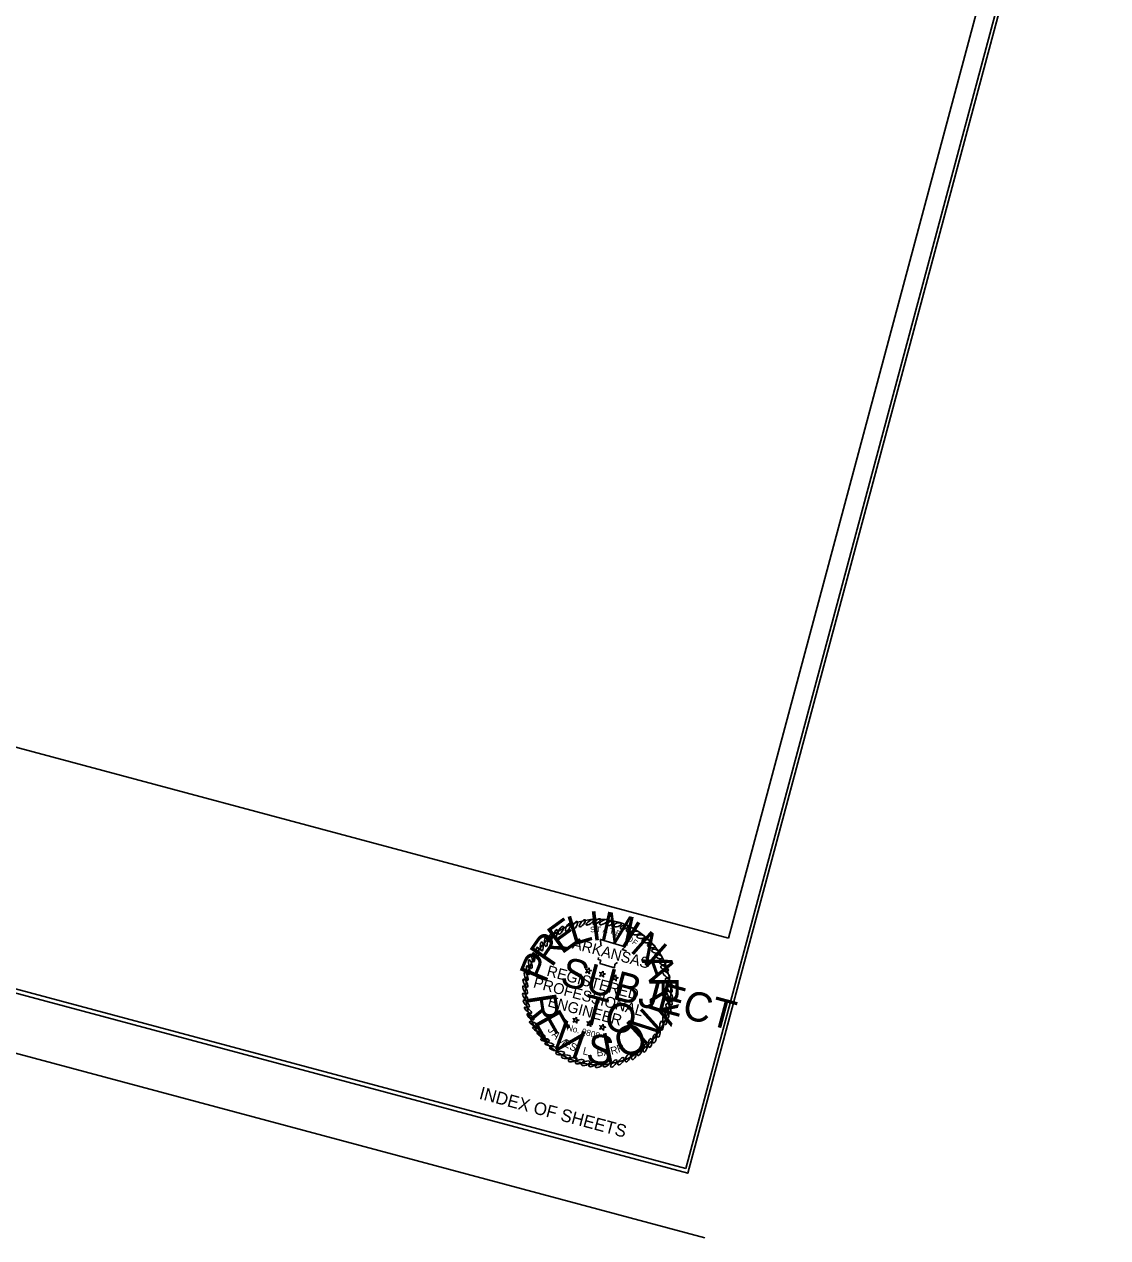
# Model space of a CAD drawing. Extents: x 1272249 to 1274802, y 195141 to 198564.
# Drawn here: x 1273526 to 1274221, y 195141 to 195920 of the extents above; entities that cross this region are included whole.
import ezdxf

# ---------------------------------------------------------------- set-up
doc = ezdxf.new("R2010")
doc.units = 0
for name, color, linetype in [('R_Border', 7, 'Continuous'), ('R_Border Notes', 7, 'Continuous'), ('R_Border PE', 7, 'Continuous'), ('R_Border Prem', 7, 'Continuous'), ('R_No Plot', 7, 'Continuous'), ('T_Drafting', 7, 'Continuous')]:
    doc.layers.add(name, color=color, linetype=linetype)

msp = doc.modelspace()

# ---------------------------------------------------------------- linework, layer by layer
at = {"layer": 'R_Border'}
for p, q in [((1273950.19, 195185.8), (1274218.04, 196185.54)), ((1272249.46, 195600.35), (1273962.36, 195141.49)), ((1273950.19, 195185.8), (1272411.61, 195598.06))]:
    msp.add_line(p, q, dxfattribs=at)
at = {"layer": 'R_Border PE'}
for points in [[(1273895.62, 195329.33), (1273895.45, 195332.76), (1273911.2, 195328.07), (1273909.45, 195326.25), (1273911.85, 195325.45), (1273911.62, 195325.2)], [(1273906.44, 195317.93), (1273904.75, 195316.87), (1273904.46, 195314.6), (1273895.05, 195317.43), (1273895.59, 195319.48), (1273893.89, 195319.93), (1273894.23, 195321.2)]]:
    msp.add_lwpolyline(points, dxfattribs=at)
for points in [[(1273888.14, 195314.64), (1273888.2, 195313.11), (1273889.61, 195312.73), (1273888.25, 195312.32), (1273888.3, 195310.74), (1273887.41, 195311.92), (1273886.01, 195311.35), (1273886.84, 195312.7), (1273885.87, 195313.74), (1273887.33, 195313.35)], [(1273897.09, 195312.4), (1273897.19, 195311.02), (1273898.5, 195310.67), (1273897.24, 195310.06), (1273897.33, 195308.63), (1273896.36, 195309.68), (1273894.99, 195309.26), (1273895.78, 195310.46), (1273894.9, 195311.63), (1273896.31, 195311.25)], [(1273905.27, 195310.05), (1273905.33, 195308.52), (1273906.74, 195308.15), (1273905.43, 195307.72), (1273905.47, 195306.14), (1273904.54, 195307.33), (1273903.14, 195306.76), (1273903.97, 195308.11), (1273903, 195309.15), (1273904.46, 195308.76)], [(1273880.13, 195282.99), (1273880.13, 195281.43), (1273881.59, 195281.04), (1273880.24, 195280.67), (1273880.29, 195279.09), (1273879.4, 195280.27), (1273878, 195279.71), (1273878.83, 195281.05), (1273877.84, 195282.04), (1273879.3, 195281.65)], [(1273889.08, 195280.75), (1273889.16, 195279.32), (1273890.48, 195278.97), (1273889.09, 195278.46), (1273889.32, 195276.99), (1273888.35, 195278.03), (1273886.98, 195277.61), (1273887.77, 195278.81), (1273886.88, 195279.94), (1273888.29, 195279.56)], [(1273897.26, 195278.4), (1273897.31, 195276.83), (1273898.72, 195276.45), (1273897.42, 195276.07), (1273897.42, 195274.5), (1273896.53, 195275.68), (1273895.13, 195275.12), (1273895.96, 195276.46), (1273894.97, 195277.45), (1273896.43, 195277.06)]]:
    msp.add_lwpolyline(points, close=True, dxfattribs=at)
for centre, major_axis, ratio in [((1273883.79, 195343.04), (-1.87, -2.18), 0.329518), ((1273888.68, 195343.79), (-2.32, -1.69), 0.329518), ((1273893.02, 195344.16), (-2.34, -1.66), 0.329518), ((1273897.51, 195343.9), (-2.78, -1.45), 0.348728), ((1273866.66, 195336.26), (-0.75, -2.78), 0.322879), ((1273869.96, 195338.55), (-1.46, -2.47), 0.391724), ((1273874.64, 195340.57), (-1.46, -2.47), 0.394697), ((1273879.09, 195341.75), (-1.46, -2.47), 0.375751), ((1273901.65, 195343.06), (-2.28, -0.97), 0.44237), ((1273906.46, 195342.19), (-2.37, -0.65), 0.475469), ((1273910.58, 195340.63), (-2.37, -0.65), 0.475469), ((1273914.34, 195338.86), (-2.37, -0.65), 0.475469), ((1273917.96, 195336.87), (-2.45, -0.11), 0.475469), ((1273857.77, 195328.25), (0.05, -2.87), 0.322879), ((1273860.47, 195331), (0.05, -2.87), 0.322879), ((1273863.55, 195333.94), (-0.75, -2.78), 0.322879), ((1273921.21, 195334.5), (-2.45, 0.19), 0.475469), ((1273924.56, 195331.75), (-2.42, 0.43), 0.475469), ((1273928.05, 195328.57), (-2.42, 0.43), 0.475469), ((1273852.44, 195321.34), (0.05, -2.87), 0.322879), ((1273855.02, 195324.85), (0.05, -2.87), 0.322879), ((1273930.59, 195325.2), (-2.35, 0.69), 0.475469), ((1273932.64, 195321.88), (-2.38, 1), 0.451028), ((1273849.13, 195313.11), (0.85, -2.75), 0.322879), ((1273850.42, 195316.96), (0.85, -2.75), 0.322879), ((1273934.88, 195317.98), (-2.36, 1.25), 0.436264), ((1273936.57, 195314.21), (-2.37, 1.46), 0.418512), ((1273847.33, 195304.67), (1.37, -2.53), 0.322879), ((1273847.78, 195309.07), (0.85, -2.75), 0.322879), ((1273937.71, 195310.16), (-2.07, 2), 0.40589), ((1273939.12, 195305.65), (-1.84, 2.21), 0.40589), ((1273847.17, 195300.38), (1.37, -2.53), 0.322879), ((1273939.58, 195301.36), (-1.6, 2.38), 0.40589), ((1273939.84, 195297.21), (-1.6, 2.38), 0.40589), ((1273847.25, 195295.75), (1.6, -2.39), 0.322879), ((1273847.9, 195291.65), (1.85, -2.2), 0.322879), ((1273939.01, 195289.09), (-1.12, 2.65), 0.40589), ((1273939.68, 195293.25), (-1.48, 2.46), 0.40589), ((1273848.95, 195287.36), (2.17, -1.88), 0.322879), ((1273850.57, 195283.12), (2.17, -1.88), 0.322879), ((1273936.65, 195280.96), (-0.44, 2.84), 0.40589), ((1273938.01, 195285.04), (-0.7, 2.79), 0.40589), ((1273852.52, 195278.62), (2.56, -1.31), 0.322879), ((1273854.52, 195275.07), (2.56, -1.31), 0.322879), ((1273932.54, 195273.03), (0.24, 2.86), 0.40589), ((1273934.65, 195277.41), (0, 2.87), 0.40589), ((1273857.29, 195271.7), (2.56, -1.31), 0.322879), ((1273859.93, 195268.3), (2.83, -0.51), 0.322879), ((1273927.34, 195266.37), (0.58, 2.81), 0.40589), ((1273930.06, 195269.19), (0.58, 2.81), 0.40589), ((1273862.66, 195265.53), (2.83, -0.51), 0.322879), ((1273865.66, 195262.76), (2.83, -0.51), 0.40589), ((1273869.59, 195259.92), (2.87, 0.03), 0.40589), ((1273916.99, 195258.29), (1.18, 2.62), 0.40589), ((1273920.6, 195261), (1.18, 2.62), 0.40589), ((1273924.15, 195263.26), (0.87, 2.74), 0.40589), ((1273873.28, 195257.55), (2.87, 0.03), 0.40589), ((1273877.6, 195255.68), (2.77, 0.77), 0.40589), ((1273882.05, 195254.42), (2.77, 0.77), 0.40589), ((1273885.98, 195253.33), (2.69, 1.02), 0.40589), ((1273890.55, 195252.74), (2.6, 1.22), 0.40589), ((1273894.86, 195252.3), (2.51, 1.41), 0.40589), ((1273899.56, 195253), (2.25, 1.79), 0.40589), ((1273904.01, 195253.24), (1.85, 2.2), 0.40589), ((1273908.58, 195254.68), (1.78, 2.25), 0.40589), ((1273912.99, 195256.84), (1.38, 2.52), 0.40589)]:
    msp.add_ellipse(centre, major_axis=major_axis, ratio=ratio, dxfattribs=at)
at = {"layer": 'R_Border Prem'}
msp.add_circle((1273893.89, 195299.06), 46.64, dxfattribs=at)
at = {"layer": 'R_No Plot'}
msp.add_lwpolyline([(1272409.01, 195596.04), (1273951.45, 195182.8), (1274220.71, 196187.64), (1272678.16, 196600.86)], close=True, dxfattribs=at)
at = {"layer": 'T_Drafting'}
msp.add_lwpolyline([(1273977.53, 195333.61), (1274177.28, 196079.07), (1272658.39, 196486.05), (1272458.65, 195740.59)], close=True, dxfattribs=at)

# ---------------------------------------------------------------- texts
at = {"layer": 'R_Border Notes'}
msp.add_text('INDEX OF SHEETS', height=8.06, rotation=345.00018, dxfattribs=at).set_placement((1273817.18, 195230.68))
at = {"layer": 'R_Border PE'}
for s, height, rotation, p in [('S', 3.48, 4.58136, (1273888.94, 195337.27)), ('T', 3.48, 359.96145, (1273892.85, 195337.47)), ('A', 3.48, 350.72162, (1273896.69, 195337.38)), ('T', 3.48, 346.10172, (1273900.81, 195336.59)), ('E', 3.48, 341.48181, (1273904.7, 195335.55)), ('ARKANSAS', 6.959, 345, (1273876.93, 195327.09)), ('O', 3.48, 327.62207, (1273911.92, 195332.52)), ('F', 3.48, 323.00216, (1273915.35, 195330.35)), ('REGISTERED', 6.959, 345, (1273860.5, 195309.58)), ('PROFESSIONAL', 6.9587, 345, (1273851.89, 195302.14)), ('ENGINEER', 6.959, 345, (1273861.14, 195289.96)), ('J', 4.84, 307.41669, (1273861.3, 195274.59)), ('No. 9808', 3.976, 345, (1273873.6, 195274.57)), ('A', 4.84, 313.01709, (1273863.83, 195271.4)), ('M', 4.84, 318.61749, (1273867.25, 195267.98)), ('E', 4.84, 329.8183, (1273871.33, 195264.75)), ('S', 4.84, 335.4187, (1273875.11, 195262.49)), ('L', 4.84, 346.61951, (1273883.76, 195259.18)), ('B', 4.84, 3.42071, (1273893.09, 195257.77)), ('A', 4.84, 9.02112, (1273897.72, 195257.94)), ('R', 4.84, 14.62152, (1273902.53, 195258.74)), ('R', 4.84, 20.22192, (1273907, 195260.05)), ('.', 4.84, 352.21991, (1273888.17, 195258.31))]:
    msp.add_text(s, height=height, rotation=rotation, dxfattribs=at).set_placement(p)
at = {"layer": 'R_Border Prem'}
for s, rotation, p in [('E', 35.98488, (1273870.45, 195322.77)), ('L', 16.66865, (1273877.76, 195328.64)), ('I', 7.01053, (1273889.86, 195331.76)), ('M', 347.69429, (1273894.34, 195332.7)), ('I', 328.37806, (1273907.21, 195329.56)), ('N', 318.71994, (1273913.73, 195325.47)), ('R', 55.30112, (1273864.3, 195314.2)), ('P', 67.60888, (1273860.25, 195303.97)), ('SUBJECT', 345, (1273868.76, 195303.82)), ('A', 289.74559, (1273921.38, 195319.97)), ('R', 270.42935, (1273926.77, 195308.73)), ('R', 278.76387, (1273848.21, 195296.61)), ('TO', 345, (1273881.96, 195279.9)), ('Y', 251.11312, (1273928.34, 195297.87)), ('E', 299.32618, (1273852.19, 195280.31)), ('N', 42.13775, (1273922.9, 195263.92)), ('V', 319.8885, (1273860.78, 195267.42)), ('O', 21.57544, (1273908.96, 195256.08)), ('I', 340.45081, (1273875.21, 195257.4)), ('S', 350.73197, (1273885.59, 195254.31)), ('I', 11.29428, (1273898.42, 195253.53))]:
    msp.add_text(s, height=18.76, rotation=rotation, dxfattribs=at).set_placement(p)

doc.saveas('drawing.dxf')
